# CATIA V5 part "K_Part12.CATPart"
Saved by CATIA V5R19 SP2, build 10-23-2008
Part number: Verin(Squelette)
Publications: "Distance_Inter_Pivot", "Point.1", "Droite_DirectionGlissière", "Droite.1", "Droite.3", "Epaisseur_Vérin", "Plan.1"
Bounding box of the stored display mesh (mm): x 6.5 to 12.5, y 0 to 160, z 0 to 10
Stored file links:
  G:\Khaled_CFAO_2011\SIL\SIL_GR1\mneves\Khaled\CAD_CATIA_Modifie\K_Part12.CATPart
  G:\Khaled_CFAO_2011\SIL\SIL_GR1\mneves\Khaled\CAD_CATIA_Modifie\K_SquePince_A_Bois.CATProduct
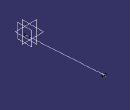
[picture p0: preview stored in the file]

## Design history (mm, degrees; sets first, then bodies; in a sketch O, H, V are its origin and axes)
External parameters (linked from other documents)
  External.Distance_Inter_Pivot = 200 mm
  `External.Epaisseur_Vérin` = 6 mm
Set1
  Point1: linked copy from another document
  Line1 "Droite_DirectionGlissière": linked copy from another document
  Plane1: linked copy from another document
Set2
  Line2: type PtDir, RefPoint Point1, Direction Line1, Start 0, End 150 {= External.Distance_Inter_Pivot *(3/4)}
  Line3: type Normal, RefPoint Point1, RefSkin Plane1, Start -3, End 3 {= `External.Epaisseur_Vérin` /2}
Body1 (main body)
